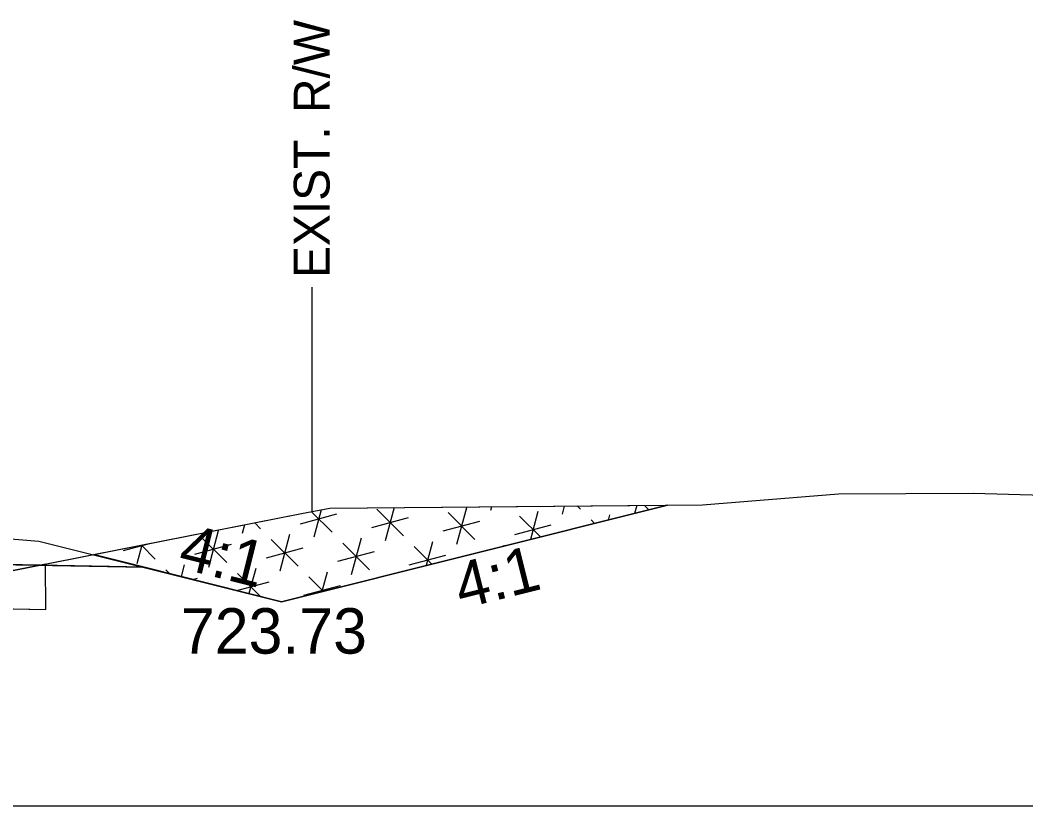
# Model space of a CAD drawing. Extents: x -26 to 4303, y -10 to 9577.
# Drawn here: x 4170.38 to 4203.55, y 1500 to 1525.91 of the extents above; entities that cross this region are included whole.
import ezdxf

# ---------------------------------------------------------------- set-up
doc = ezdxf.new("R2010")
doc.units = 0
for name, color, linetype in [('Old_Level_2', 7, 'Continuous'), ('Pattern 3', 7, 'Continuous'), ('Prop CMT Pvmt Course 2 Wedge', 7, 'Continuous'), ('Prop CMT Pvmt Wedge Surface 1', 7, 'Continuous'), ('Prop CMT Slope Grass', 7, 'Continuous'), ('Prop Road Sect_ Recs - UC Shallow (Outline)', 7, 'Continuous'), ('Prop Shade Light', 7, 'Continuous'), ('Prop XS DDE Elevations', 7, 'Continuous'), ('Prop XS Ditch Standard Text', 7, 'Continuous'), ('Prop XS Hydro Elevations', 7, 'Continuous'), ('Prop XS Side Slope Text', 7, 'Continuous')]:
    doc.layers.add(name, color=color, linetype=linetype)

msp = doc.modelspace()

# ---------------------------------------------------------------- linework, layer by layer
at = {"layer": 'Old_Level_2'}
msp.add_line((4150, 1500), (4300, 1500), dxfattribs=at)
msp.add_line((4150, 1500), (4300, 1500), dxfattribs=at)
at = {"layer": 'Pattern 3'}
for p, q in [((4182.712, 1509.839), (4182.418, 1508.742)), ((4185.098, 1509.831), (4184.774, 1508.624)), ((4185.926, 1509.866), (4185.893, 1509.743)), ((4188.32, 1509.887), (4188.25, 1509.625)), ((4188.749, 1509.891), (4188.853, 1509.786)), ((4190.714, 1509.908), (4190.643, 1509.645)), ((4190.968, 1509.91), (4191.115, 1509.763)), ((4179.619, 1509.303), (4180.827, 1509.626)), ((4179.986, 1509.702), (4180.665, 1509.023)), ((4180.303, 1509.764), (4180.061, 1508.861)), ((4181.976, 1509.184), (4183.183, 1509.508)), ((4182.138, 1509.788), (4183.022, 1508.904)), ((4184.494, 1509.67), (4185.378, 1508.786)), ((4186.851, 1509.551), (4187.534, 1508.868)), ((4187.454, 1509.713), (4187.206, 1508.786)), ((4189.811, 1509.595), (4189.766, 1509.426)), ((4177.782, 1509.268), (4177.705, 1508.979)), ((4178.116, 1509.334), (4178.309, 1509.141)), ((4184.332, 1509.066), (4185.54, 1509.389)), ((4186.689, 1508.947), (4187.896, 1509.271)), ((4189.207, 1509.433), (4189.324, 1509.316)), ((4176.306, 1508.906), (4177.19, 1508.022)), ((4176.909, 1509.068), (4176.586, 1507.86)), ((4179.266, 1508.949), (4178.942, 1507.742)), ((4181.622, 1508.831), (4181.299, 1507.623)), ((4173.787, 1508.421), (4174.644, 1508.65)), ((4174.396, 1508.601), (4174.229, 1507.979)), ((4174.376, 1508.597), (4174.833, 1508.14)), ((4176.144, 1508.302), (4177.351, 1508.626)), ((4178.5, 1508.184), (4179.708, 1508.507)), ((4178.662, 1508.787), (4179.546, 1507.904)), ((4181.019, 1508.669), (4181.902, 1507.785)), ((4183.375, 1508.551), (4183.953, 1507.973)), ((4183.979, 1508.712), (4183.768, 1507.927)), ((4186.335, 1508.594), (4186.328, 1508.566)), ((4180.857, 1508.065), (4182.064, 1508.389)), ((4183.213, 1507.947), (4184.421, 1508.27)), ((4185.732, 1508.432), (4185.743, 1508.42)), ((4175.79, 1507.949), (4175.687, 1507.563)), ((4178.147, 1507.83), (4177.925, 1507.003)), ((4175.187, 1507.787), (4175.319, 1507.655)), ((4176.077, 1507.465), (4176.232, 1507.507)), ((4177.543, 1507.668), (4178.303, 1506.909)), ((4179.9, 1507.55), (4180.372, 1507.077)), ((4180.503, 1507.712), (4180.331, 1507.067)), ((4177.525, 1507.103), (4178.589, 1507.388)), ((4179.738, 1506.946), (4180.945, 1507.27))]:
    msp.add_line(p, q, dxfattribs=at)
msp.add_lwpolyline([(4191.729, 1509.917), (4179, 1506.734), (4172.795, 1508.286), (4179.653, 1509.637), (4180.59, 1509.82)], close=True, dxfattribs=at)
at = {"layer": 'Prop CMT Pvmt Course 2 Wedge'}
msp.add_lwpolyline([(4169, 1508.894), (4171, 1508.734), (4179, 1506.734), (4191.729, 1509.917)], dxfattribs=at)
at = {"layer": 'Prop CMT Pvmt Wedge Surface 1'}
msp.add_line((4166.982, 1508.018), (4174.465, 1507.868), dxfattribs=at)
at = {"layer": 'Prop CMT Slope Grass'}
msp.add_lwpolyline([(4167.739, 1507.29), (4179.653, 1509.637), (4180.59, 1509.82), (4192.881, 1509.927), (4197.367, 1510.294), (4201.803, 1510.308), (4211.528, 1510.043)], dxfattribs=at)
at = {"layer": 'Prop Road Sect_ Recs - UC Shallow (Outline)'}
msp.add_lwpolyline([(4161.69, 1506.665), (4171.221, 1506.475), (4171.218, 1507.975), (4167.739, 1507.29), (4163.72, 1508.125), (4161.72, 1508.165)], close=True, dxfattribs=at)
at = {"layer": 'Prop Shade Light'}
for p, q in [((4171.221, 1506.475), (4171.218, 1507.975)), ((4161.69, 1506.665), (4171.221, 1506.475))]:
    msp.add_line(p, q, dxfattribs=at)
msp.add_lwpolyline([(4171.218, 1507.975), (4167.739, 1507.29), (4163.72, 1508.125), (4161.72, 1508.165)], dxfattribs=at)
at = {"layer": 'Prop XS DDE Elevations'}
for points in [[(4179.653, 1509.637), (4180.59, 1509.82), (4191.729, 1509.917), (4179, 1506.734), (4174.465, 1507.868), (4172.795, 1508.286)], [(4172.795, 1508.286), (4174.465, 1507.868), (4171.025, 1507.937)], [(4163.944, 1508.079), (4167.739, 1507.29), (4171.025, 1507.937), (4166.982, 1508.018)]]:
    msp.add_lwpolyline(points, close=True, dxfattribs=at)
at = {"layer": 'Prop XS Ditch Standard Text'}
msp.add_line((4179.993, 1517.105), (4179.993, 1509.703), dxfattribs=at)

# ---------------------------------------------------------------- texts
msp.add_text('EXIST. R/W', height=1.1811, rotation=90, dxfattribs=at).set_placement((4180.583, 1517.407))
at = {"layer": 'Prop XS Hydro Elevations'}
msp.add_text('723.73', height=1.5, dxfattribs=at).set_placement((4175.681, 1505.02))
at = {"layer": 'Prop XS Side Slope Text'}
for rotation, p in [(345.9638, (4175.536, 1507.863)), (14.0362, (4184.925, 1506.486))]:
    msp.add_text('4:1', height=1.5, rotation=rotation, dxfattribs=at).set_placement(p)

doc.saveas('drawing.dxf')
